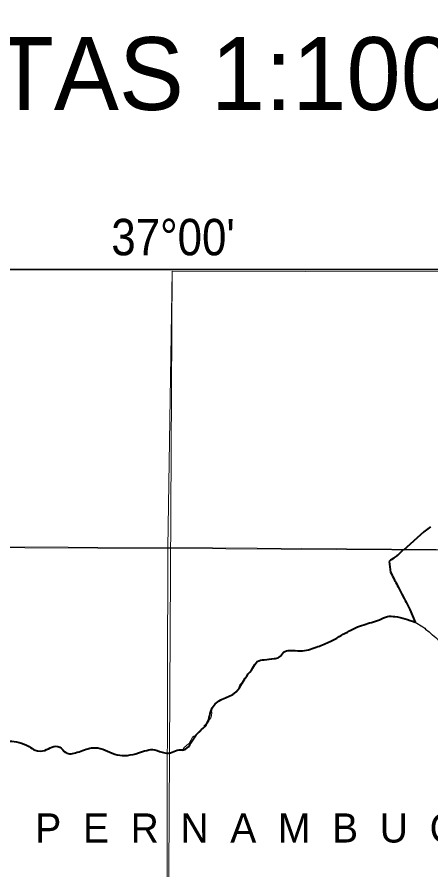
# Model space of a CAD drawing. Extents: x 553962 to 842807, y 8883888 to 9032388.
# Drawn here: x 605530 to 611208, y 8916524 to 8928234 of the extents above; entities that cross this region are included whole.
import ezdxf
from ezdxf.enums import TextEntityAlignment as Align

# ---------------------------------------------------------------- set-up
doc = ezdxf.new("R2010")
doc.units = 0
doc.header["$LTSCALE"] = 200
doc.layers.add('6', color=7, linetype='Continuous', lineweight=13)

msp = doc.modelspace()

# ---------------------------------------------------------------- linework, layer by layer
at = {"layer": '6', "lineweight": 35}
msp.add_lwpolyline([(574695.3, 8924769.6), (626625.7, 8924769.6), (626625.7, 8896026.7), (574695.3, 8896026.7)], close=True, dxfattribs=at)
at = {"layer": '6'}
for points in [[(607657.7, 8924743.3), (607574.2, 8909874.9), (607492.3, 8896026.7)], [(574684.9, 8921064.7), (596639.8, 8920989.8), (607636.3, 8920937.2), (626625.7, 8920820.5)], [(608653.2, 8919135.4), (608627.5, 8919108.1), (608598.7, 8919080.5), (608588.5, 8919064.1), (608579.3, 8919042.5), (608574.7, 8919033.7)], [(608214.8, 8918763.2), (608214.6, 8918763), (608203.2, 8918740.5), (608199.9, 8918729.1), (608198.5, 8918716.4), (608201.2, 8918682.1), (608198.2, 8918648.6), (608196.3, 8918636.7), (608192.6, 8918626.3), (608186.9, 8918613.7), (608176.4, 8918594.3), (608159.6, 8918568.5), (608149.7, 8918555.2), (608130, 8918535), (608091.6, 8918499.7)], [(608068.8, 8918461.3), (608049.2, 8918432.6), (608029, 8918410.6), (608021.3, 8918406.2), (608021.3, 8918406.2), (608015.4, 8918401.8), (608006.1, 8918391.9), (607991.4, 8918380.3), (607954.4, 8918358.8), (607938.1, 8918345.2), (607920.6, 8918312.8), (607912.3, 8918300.6), (607906.8, 8918287.1), (607885.5, 8918256.2), (607882.4, 8918252.9), (607860.3, 8918235.8), (607851.7, 8918227.1), (607824.1, 8918202.7), (607810.2, 8918183.2), (607795.2, 8918160)]]:
    msp.add_lwpolyline(points, dxfattribs=at)
for points in [[(607657.7, 8924743.3), (618663, 8924716.1), (618636, 8920869.6), (607600.8, 8920952.4)], [(607600.8, 8920952.4), (596639.8, 8920989.8), (596608.8, 8909934.4), (607569.8, 8909894.9)]]:
    msp.add_lwpolyline(points, close=True, dxfattribs=at)
at = {"layer": '6', "lineweight": 40}
for points in [[(611201.4, 8921234.4), (611108.7, 8921166), (610832.8, 8920916.1)], [(610827.8, 8920917.6), (610823, 8920914), (610762.1, 8920855.7), (610749.5, 8920841.5), (610740.9, 8920836.9), (610713, 8920816.2), (610698.2, 8920806.3), (610662.6, 8920780.4), (610653.5, 8920774.9), (610648.2, 8920770.6), (610634.6, 8920757.1)], [(610634.6, 8920757.1), (610655.2, 8920612.5), (610665.4, 8920591.1), (610678.2, 8920567.9), (610682, 8920558.9), (610694.4, 8920535.7), (610709.7, 8920504), (610719.3, 8920486.7), (610726, 8920471.9), (610739.4, 8920447.4), (610745.8, 8920433.2), (610758.2, 8920410.6), (610809.7, 8920308.8), (610840.7, 8920249.1), (610850, 8920232.8), (610852.7, 8920225.4), (610867.4, 8920199.1), (610898.1, 8920137.8), (610910.3, 8920115.9), (610916.7, 8920101.6), (610989.7, 8919925.2)]]:
    msp.add_lwpolyline(points, dxfattribs=at)
at = {"layer": '6', "lineweight": 25}
msp.add_lwpolyline([(610989.7, 8919925.2), (611098.4, 8919862.7), (611123, 8919843.5), (611135.6, 8919830.6), (611185.4, 8919791.8), (611226, 8919753.4), (611227.9, 8919750.7), (611254.6, 8919731.6), (611274, 8919715.5), (611334.2, 8919651.6), (611344.9, 8919639.3), (611360, 8919618.6), (611370.7, 8919602.3), (611407.8, 8919535.5), (611413.8, 8919514.2), (611418, 8919503.3), (611429.4, 8919467.6), (611437.3, 8919447.9), (611446.9, 8919416.8), (611465.8, 8919371.6)], dxfattribs=at)
at = {"layer": '6', "lineweight": 40}
msp.add_spline([(605233.4, 8918291.8), (605425.1, 8918291.8), (605556.8, 8918274.6), (605694.1, 8918217.3), (605780, 8918168.6), (605911.6, 8918165.8), (606008.9, 8918211.6), (606114.8, 8918211.6), (606197.8, 8918134.3), (606353.7, 8918138.6), (606551.2, 8918198.7), (606637.1, 8918198.7), (606903.2, 8918104.2), (607195.1, 8918130), (607418.3, 8918172.9), (607555.7, 8918130), (607658.7, 8918138.6), (607753.1, 8918172.9), (607813.2, 8918172.9), (607967.8, 8918353.3), (608139.5, 8918542.3), (608208.1, 8918748.4), (608345.5, 8918868.7), (608508.6, 8918946), (608680.3, 8919186.5), (608766.2, 8919298.2), (608826.3, 8919384.1), (608920.7, 8919409.8), (609058.1, 8919427), (609126.8, 8919444.2), (609186.8, 8919512.9), (609272.7, 8919538.7), (609418.7, 8919530.1), (609633.3, 8919581.6), (609805, 8919650.3), (609950.9, 8919727.6), (610174.2, 8919847.9), (610285.8, 8919890.8), (610500.4, 8919959.5), (610612, 8920002.5), (610715, 8920002.5), (610989.7, 8919925.2)], degree=3, dxfattribs=at)

# ---------------------------------------------------------------- texts
at = {"layer": '6'}
msp.add_text('ARTICULAÇÃO DAS CARTAS 1:100.000', height=1000, dxfattribs=at).set_placement((601765.5, 8926958.2), align=Align.CENTER)
at = {"layer": '6', "width": 0.9}
msp.add_text("37°00'", height=500, dxfattribs=at).set_placement((607670.1, 8924963.2), align=Align.CENTER)
at = {"layer": '6'}
msp.add_text('P  E  R  N  A  M  B  U  C  O', height=400, dxfattribs=at).set_placement((605780.3, 8916899.9))

doc.saveas('drawing.dxf')
